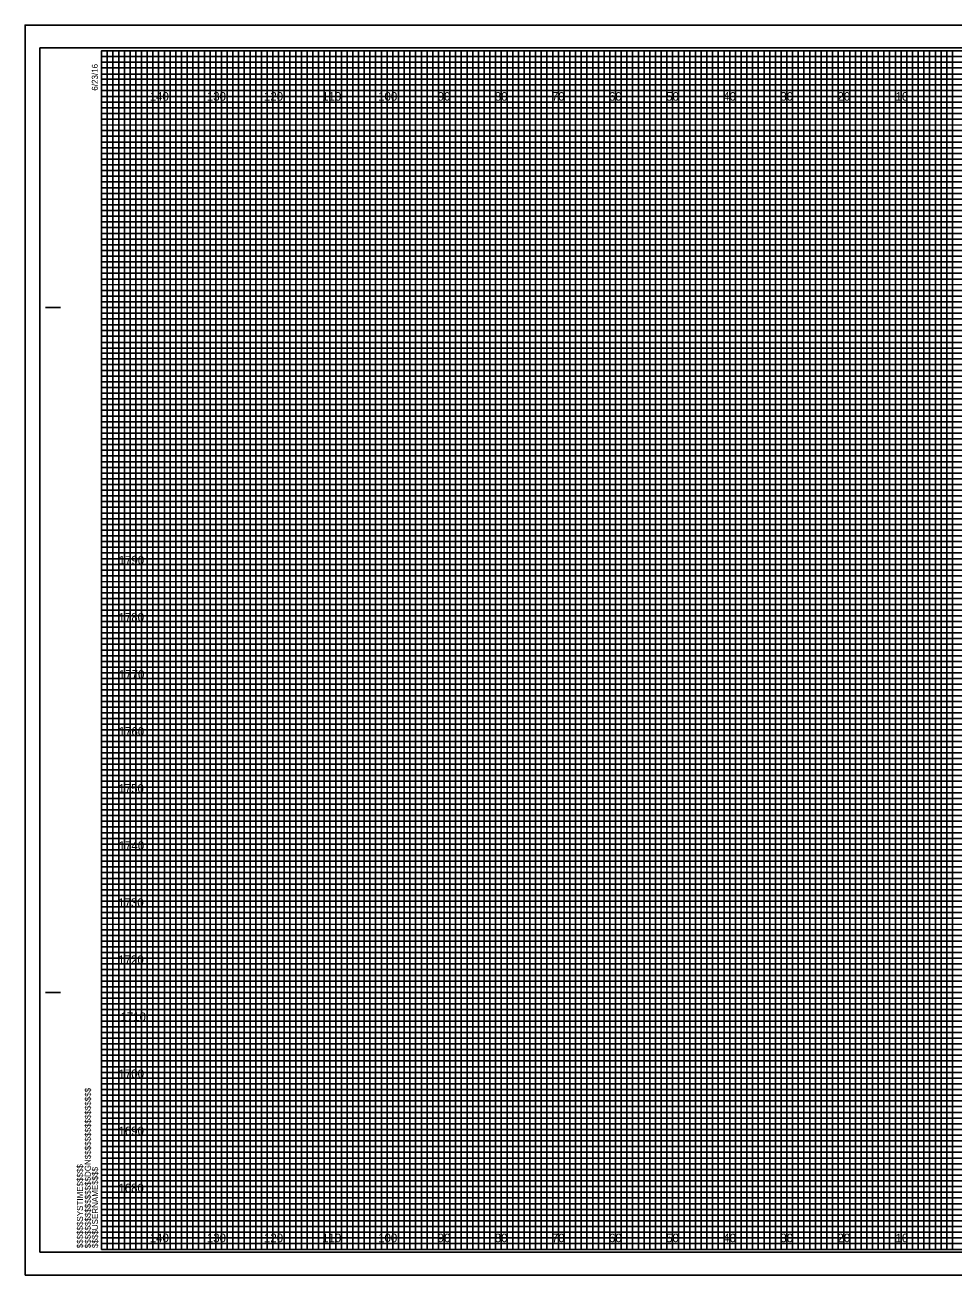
# Model space of a CAD drawing. Extents: x 1443 to 2205, y -29 to 5484.
# Drawn here: x 1867.8 to 2030.5, y 631.1 to 850.1 of the extents above; entities that cross this region are included whole.
import ezdxf

# ---------------------------------------------------------------- set-up
doc = ezdxf.new("R2010")
doc.units = 0
for name, color, linetype in [('Pattern 3', 7, 'Continuous'), ('Prop Retaining Wall', 7, 'Continuous'), ('Prop XS DDE Earthwork Shape', 7, 'Continuous'), ('Prop XS DDE Slope Text', 7, 'Continuous'), ('Prop XS DDE Text', 7, 'Continuous'), ('Prop XS Earthwork Shape', 7, 'Continuous'), ('Prop XS Retaining Wall', 7, 'Continuous'), ('Prop XS Station Labels', 7, 'Continuous'), ('Prop XS Temporary Shoring', 7, 'Continuous'), ('Raster_Level_0', 7, 'Continuous'), ('Scratch_Level_3', 7, 'Continuous')]:
    doc.layers.add(name, color=color, linetype=linetype)

msp = doc.modelspace()

# ---------------------------------------------------------------- linework, layer by layer
at = {"layer": 'Pattern 3'}
for p, q in [((2204.52, 850.05), (1867.82, 850.05)), ((1867.82, 850.05), (1867.82, 631.05)), ((1867.82, 631.05), (2204.52, 631.05))]:
    msp.add_line(p, q, dxfattribs=at)
at = {"layer": 'Prop Retaining Wall'}
for p, q in [((1881.22, 844.55), (2141.22, 844.55)), ((2141.22, 843.53), (1881.22, 843.53)), ((1881.22, 843.53), (1881.22, 842.55)), ((1881.22, 842.55), (2141.22, 842.55)), ((2141.22, 841.44), (1881.22, 841.44)), ((1881.22, 841.44), (1881.22, 839.55)), ((1881.22, 839.55), (2201.22, 839.55))]:
    msp.add_line(p, q, dxfattribs=at)
for points in [[(1881.22, 838.55), (2151.22, 838.55), (2201.22, 838.55), (2201.22, 837.55), (1881.22, 837.55)], [(1881.22, 836.55), (2201.22, 836.55), (2201.22, 834.55), (1881.22, 834.55)], [(1881.22, 833.55), (2201.22, 833.55), (2201.22, 832.55), (1881.22, 832.53)], [(1881.22, 831.55), (2201.22, 831.55), (2201.22, 829.55), (1881.22, 829.55)], [(1881.22, 828.55), (2201.22, 828.55), (2201.22, 827.55), (1881.22, 827.55)], [(1881.22, 826.55), (2201.22, 826.55), (2201.22, 824.55), (1881.22, 824.55)], [(1881.22, 823.55), (2201.22, 823.55), (2201.22, 822.55), (1881.22, 822.55)], [(1881.22, 821.55), (2201.22, 821.55), (2201.22, 819.55), (1881.22, 819.55)], [(1881.22, 818.55), (2201.22, 818.55), (2201.22, 817.55), (1881.22, 817.55)], [(1881.22, 816.55), (2201.22, 816.55), (2201.22, 814.55), (1881.22, 814.55)], [(1881.22, 813.55), (2201.22, 813.55), (2201.22, 812.55), (1881.22, 812.55)], [(1881.22, 811.55), (2201.22, 811.55), (2201.22, 809.5), (2201.22, 808.55), (2201.22, 807.55), (1881.22, 807.55)], [(1881.22, 809.55), (2201.22, 809.55), (2201.22, 808.55), (1881.22, 808.55)], [(1881.22, 806.55), (2201.22, 806.55), (2201.22, 804.55), (1881.22, 804.58)], [(1881.22, 804.58), (2201.22, 804.55), (2201.22, 803.55), (1881.22, 803.55)], [(1881.22, 802.55), (2201.22, 802.55), (2201.22, 801.55), (1881.22, 801.55)], [(1881.22, 799.55), (2201.22, 799.55), (2201.22, 798.55), (1881.22, 798.55)], [(1881.22, 797.55), (2201.22, 797.55), (2201.22, 796.55), (1881.22, 796.55)], [(1881.15, 794.44), (2201.22, 794.44), (2201.22, 793.43), (1881.15, 793.43)], [(1881.22, 792.55), (2201.22, 792.55), (2201.22, 791.55), (1881.22, 791.55)], [(1881.22, 789.55), (2201.22, 789.55), (2201.22, 788.55), (1881.22, 788.55)], [(1881.22, 787.55), (2201.22, 787.55), (2201.22, 786.55), (1881.22, 786.55)], [(1881.22, 784.55), (2201.22, 784.55), (2201.22, 783.55), (1881.22, 783.55)], [(1881.22, 782.55), (2201.22, 782.55), (2201.22, 781.55), (1881.22, 781.55)], [(1881.22, 779.55), (2201.22, 779.55), (2201.22, 778.55), (1881.22, 778.55)], [(1881.22, 777.55), (2201.22, 777.55), (2201.22, 776.55), (1881.22, 776.55)], [(1881.22, 774.55), (2201.22, 774.55), (2201.21, 773.53), (1881.22, 773.55)], [(1881.22, 772.55), (2201.22, 772.55), (2201.22, 771.55), (1881.22, 771.55)], [(1881.22, 769.55), (2201.22, 769.55), (2201.22, 768.55), (1881.22, 768.55)], [(1881.22, 767.55), (2201.22, 767.55), (2201.22, 766.55), (1881.22, 766.55)], [(1881.22, 764.55), (2201.22, 764.55), (2201.22, 763.55), (1881.22, 763.55)], [(1881.22, 762.55), (2201.22, 762.55), (2201.22, 761.55), (1881.22, 761.55)], [(1881.22, 759.55), (2201.22, 759.55), (2201.22, 758.55), (1881.22, 758.55)], [(1881.22, 757.55), (2201.22, 757.55), (2201.22, 756.55), (1881.22, 756.55)], [(1881.22, 754.55), (2201.22, 754.55), (2201.22, 753.55), (1881.22, 753.55)], [(1881.22, 752.54), (2201.29, 752.46), (2201.22, 751.55), (1881.22, 751.55)], [(1881.22, 749.55), (2201.22, 749.55), (2201.22, 748.55), (1881.22, 748.55)], [(1881.22, 747.55), (2201.22, 747.55), (2201.22, 746.55), (1881.22, 746.55)], [(1881.22, 744.55), (2201.22, 744.55), (2201.22, 743.55), (1881.22, 743.55)], [(1881.22, 742.55), (2201.22, 742.55), (2201.22, 741.55), (1881.22, 741.55)], [(1881.22, 739.55), (2201.22, 739.55), (2201.22, 738.55), (1881.22, 738.55)], [(1881.22, 737.55), (2201.22, 737.55), (2201.22, 736.55), (1881.22, 736.55)], [(1881.22, 734.55), (2201.22, 734.55), (2201.22, 733.55), (1881.22, 733.55)], [(1881.22, 732.55), (2201.22, 732.55), (2201.22, 731.55), (1881.22, 731.55)], [(1881.22, 729.55), (2201.22, 729.55), (2201.22, 728.55), (1881.22, 728.55)], [(1881.22, 727.55), (2201.22, 727.55), (2201.22, 726.55), (1881.22, 726.55)], [(1881.22, 724.55), (2201.22, 724.55), (2201.22, 723.55), (1881.22, 723.55)], [(1881.22, 722.55), (2201.22, 722.55), (2201.22, 721.55), (1881.22, 721.55)], [(1881.22, 719.55), (2201.22, 719.55), (2201.22, 718.55), (1881.22, 718.55)], [(1881.22, 717.55), (2201.22, 717.55), (2201.22, 716.55), (1881.22, 716.55)], [(1881.22, 714.55), (2201.22, 714.55), (2201.21, 713.53), (1881.22, 713.55)], [(1881.22, 712.55), (2201.22, 712.55), (2201.22, 711.55), (1881.22, 711.55)], [(1881.22, 709.55), (2201.22, 709.55), (2201.22, 708.55), (1881.22, 708.55)], [(1881.22, 707.55), (2201.22, 707.55), (2201.22, 706.55), (1881.22, 706.55)], [(1881.22, 704.55), (2201.22, 704.55), (2201.22, 703.55), (1881.22, 703.55)], [(1881.22, 702.55), (2201.22, 702.55), (2201.22, 701.55), (1881.22, 701.55)], [(1881.22, 699.55), (2201.22, 699.55), (2201.22, 698.55), (1881.22, 698.55)], [(1881.22, 697.55), (2201.22, 697.55), (2201.22, 696.55), (1881.22, 696.55)], [(1881.22, 694.55), (2201.22, 694.55), (2201.22, 693.55), (1881.22, 693.55)], [(1881.22, 692.54), (2201.29, 692.46), (2201.22, 691.55), (1881.22, 691.55)], [(1881.22, 689.55), (2201.22, 689.55), (2201.22, 688.55), (1881.22, 688.55)], [(1881.22, 687.55), (2201.22, 687.55), (2201.22, 686.55), (1881.22, 686.55)], [(1881.22, 684.55), (2201.22, 684.55), (2201.22, 683.55), (1881.22, 683.55)], [(1881.22, 682.55), (2201.22, 682.55), (2201.22, 681.55), (1881.22, 681.55)], [(1881.22, 679.55), (2201.22, 679.55), (2201.22, 678.55), (1881.22, 678.55)], [(1881.22, 677.55), (2201.22, 677.55), (2201.22, 676.55), (1881.22, 676.55)], [(1881.22, 674.55), (2201.22, 674.55), (2201.22, 673.55), (1881.22, 673.55)], [(1881.22, 672.55), (2201.22, 672.55), (2201.22, 671.55), (1881.22, 671.55)], [(1881.22, 669.55), (2201.22, 669.55), (2201.22, 668.55), (1881.22, 668.55)], [(1881.22, 667.55), (2201.22, 667.55), (2201.22, 666.55), (1881.22, 666.55)], [(1881.22, 664.55), (2201.22, 664.55), (2201.22, 663.55), (1881.22, 663.55)], [(1881.22, 662.55), (2201.22, 662.55), (2201.22, 661.55), (1881.22, 661.55)], [(1881.22, 659.55), (2201.22, 659.55), (2201.22, 658.55), (1881.22, 658.55)], [(1881.22, 657.55), (2201.22, 657.55), (2201.22, 656.55), (1881.22, 656.55)], [(1881.22, 654.55), (2201.22, 654.55), (2201.22, 653.55), (1881.22, 653.55)], [(1881.22, 652.55), (2201.22, 652.55), (2201.22, 651.55), (1881.22, 651.55)], [(1881.22, 649.55), (2201.22, 649.55), (2201.22, 648.55), (1881.22, 648.55)], [(1881.22, 647.55), (2201.22, 647.55), (2201.22, 646.55), (1881.22, 646.55)], [(1881.22, 644.55), (2201.22, 644.55), (2201.22, 643.55), (1881.22, 643.55)], [(1881.22, 642.55), (2201.22, 642.55), (2201.22, 641.55), (1881.22, 641.55)], [(1881.22, 639.55), (2201.22, 639.55), (2201.22, 638.55), (1881.22, 638.55)], [(1881.22, 637.55), (2201.22, 637.55), (2201.22, 636.55), (1881.22, 636.55)]]:
    msp.add_lwpolyline(points, dxfattribs=at)
at = {"layer": 'Prop XS DDE Earthwork Shape'}
msp.add_lwpolyline([(1870.42, 635.05), (2203.62, 635.05), (2203.62, 846.05), (1870.42, 846.05)], close=True, dxfattribs=at)
at = {"layer": 'Prop XS DDE Slope Text'}
for points in [[(1881.22, 635.55), (1882.22, 635.55), (1882.22, 845.55), (1883.22, 845.55), (1883.22, 635.55)], [(1883.22, 635.55), (1884.22, 635.55), (1884.22, 845.55), (1885.22, 845.55), (1885.22, 635.55)], [(1886.22, 635.55), (1887.22, 635.55), (1887.22, 845.55), (1888.22, 845.55), (1888.22, 635.55)], [(1888.22, 635.55), (1889.22, 635.55), (1889.22, 845.55), (1890.22, 845.55), (1890.22, 635.55)], [(1891.22, 635.55), (1892.22, 635.55), (1892.22, 845.55), (1893.22, 845.55), (1893.22, 635.55)], [(1893.22, 635.55), (1894.22, 635.55), (1894.22, 845.55), (1895.22, 845.55), (1895.22, 635.55)], [(1896.22, 635.55), (1897.22, 635.55), (1897.22, 845.55), (1898.22, 845.55), (1898.22, 635.55)], [(1898.22, 635.55), (1899.22, 635.55), (1899.22, 845.55), (1900.22, 845.55), (1900.22, 635.55)], [(1901.22, 635.55), (1902.22, 635.55), (1902.22, 845.55), (1903.22, 845.55), (1903.22, 635.55)], [(1903.22, 635.55), (1904.22, 635.55), (1904.22, 845.55), (1905.22, 845.55), (1905.22, 635.55)], [(1906.22, 635.55), (1907.22, 635.55), (1907.22, 845.55), (1908.22, 845.55), (1908.22, 635.55)], [(1908.22, 635.55), (1909.22, 635.55), (1909.22, 845.55), (1910.22, 845.55), (1910.22, 635.55)], [(1911.22, 635.55), (1912.22, 635.55), (1912.22, 845.55), (1913.22, 845.55), (1913.22, 635.55)], [(1913.22, 635.55), (1914.22, 635.55), (1914.22, 845.55), (1915.22, 845.55), (1915.22, 635.55)], [(1916.22, 635.55), (1917.22, 635.55), (1917.22, 845.55), (1918.22, 845.55), (1918.22, 635.55)], [(1918.22, 635.55), (1919.22, 635.55), (1919.22, 845.55), (1920.22, 845.55), (1920.22, 635.55)], [(1921.22, 635.55), (1922.22, 635.55), (1922.22, 845.55), (1923.22, 845.55), (1923.22, 635.55)], [(1923.22, 635.55), (1924.22, 635.55), (1924.22, 845.55), (1925.22, 845.55), (1925.22, 635.55)], [(1926.22, 635.55), (1927.22, 635.55), (1927.22, 845.55), (1928.22, 845.55), (1928.22, 635.55)], [(1928.22, 635.55), (1929.22, 635.55), (1929.22, 845.55), (1930.22, 845.55), (1930.22, 635.55)], [(1931.22, 635.55), (1932.22, 635.55), (1932.22, 845.55), (1933.22, 845.55), (1933.22, 635.55)], [(1933.22, 635.55), (1934.22, 635.55), (1934.22, 845.55), (1935.22, 845.55), (1935.22, 635.55)], [(1936.22, 635.55), (1937.22, 635.55), (1937.22, 845.55), (1938.22, 845.55), (1938.22, 635.55)], [(1938.22, 635.55), (1939.22, 635.55), (1939.22, 845.55), (1940.22, 845.55), (1940.22, 635.55)], [(1941.22, 635.55), (1942.22, 635.55), (1942.22, 845.55), (1943.22, 845.55), (1943.22, 635.55)], [(1943.22, 635.55), (1944.22, 635.55), (1944.22, 845.55), (1945.22, 845.55), (1945.22, 635.55)], [(1946.22, 635.55), (1947.22, 635.55), (1947.22, 845.55), (1948.22, 845.55), (1948.22, 635.55)], [(1948.22, 635.55), (1949.22, 635.55), (1949.22, 845.55), (1950.22, 845.55), (1950.22, 635.55)], [(1951.22, 635.55), (1952.22, 635.55), (1952.22, 845.55), (1953.22, 845.55), (1953.22, 635.55)], [(1953.22, 635.55), (1954.22, 635.55), (1954.22, 845.55), (1955.22, 845.55), (1955.22, 635.55)], [(1956.22, 635.55), (1957.22, 635.55), (1957.22, 845.55), (1958.22, 845.55), (1958.22, 635.55)], [(1958.22, 635.55), (1959.22, 635.55), (1959.22, 845.55), (1960.22, 845.55), (1960.22, 635.55)], [(1961.22, 635.55), (1962.22, 635.55), (1962.22, 845.55), (1963.22, 845.55), (1963.22, 635.55)], [(1963.22, 635.55), (1964.22, 635.55), (1964.22, 845.55), (1965.22, 845.55), (1965.22, 635.55)], [(1966.22, 635.55), (1967.22, 635.55), (1967.22, 845.55), (1968.22, 845.55), (1968.22, 635.55)], [(1968.22, 635.55), (1969.22, 635.55), (1969.22, 845.55), (1970.22, 845.55), (1970.22, 635.55)], [(1971.22, 635.55), (1972.22, 635.55), (1972.22, 845.55), (1973.22, 845.55), (1973.22, 635.55)], [(1973.22, 635.55), (1974.22, 635.55), (1974.22, 845.55), (1975.22, 845.55), (1975.22, 635.55)], [(1976.22, 635.55), (1977.22, 635.55), (1977.22, 845.55), (1978.22, 845.55), (1978.22, 635.55)], [(1978.22, 635.55), (1979.22, 635.55), (1979.22, 845.55), (1980.22, 845.55), (1980.22, 635.55)], [(1981.22, 635.55), (1982.22, 635.55), (1982.22, 845.55), (1983.22, 845.55), (1983.22, 635.55)], [(1983.22, 635.55), (1984.22, 635.55), (1984.22, 845.55), (1985.22, 845.55), (1985.22, 635.55)], [(1986.22, 635.55), (1987.22, 635.55), (1987.22, 845.55), (1988.22, 845.55), (1988.22, 635.55)], [(1988.22, 635.55), (1989.22, 635.55), (1989.22, 845.55), (1990.22, 845.55), (1990.22, 635.55)], [(1991.22, 635.55), (1992.22, 635.55), (1992.22, 845.55), (1993.22, 845.55), (1993.22, 635.55)], [(1993.22, 635.55), (1994.22, 635.55), (1994.22, 845.55), (1995.22, 845.55), (1995.22, 635.55)], [(1996.22, 635.55), (1997.22, 635.55), (1997.22, 845.55), (1998.22, 845.55), (1998.22, 635.55)], [(1998.22, 635.55), (1999.22, 635.55), (1999.22, 845.55), (2000.22, 845.55), (2000.22, 635.55)], [(2001.22, 635.55), (2002.22, 635.55), (2002.22, 845.55), (2003.22, 845.55), (2003.22, 635.55)], [(2003.22, 635.55), (2004.22, 635.55), (2004.22, 845.55), (2005.22, 845.55), (2005.22, 635.55)], [(2006.22, 635.55), (2007.22, 635.55), (2007.22, 845.55), (2008.22, 845.55), (2008.22, 635.55)], [(2008.22, 635.55), (2009.22, 635.55), (2009.22, 845.55), (2010.22, 845.55), (2010.22, 635.55)], [(2011.22, 635.55), (2012.22, 635.55), (2012.22, 845.55), (2013.22, 845.55), (2013.22, 635.55)], [(2013.22, 635.55), (2014.22, 635.55), (2014.22, 845.55), (2015.22, 845.55), (2015.22, 635.55)], [(2016.22, 635.55), (2017.22, 635.55), (2017.22, 845.55), (2018.22, 845.55), (2018.22, 635.55)], [(2018.22, 635.55), (2019.22, 635.55), (2019.22, 845.55), (2020.22, 845.55), (2020.22, 635.55)], [(2021.22, 635.55), (2022.22, 635.55), (2022.22, 845.55), (2023.22, 845.55), (2023.22, 635.55)], [(2023.22, 635.55), (2024.22, 635.55), (2024.22, 845.55), (2025.22, 845.55), (2025.22, 635.55)], [(2026.22, 635.55), (2027.22, 635.55), (2027.22, 845.55), (2028.22, 845.55), (2028.22, 635.55)], [(2028.22, 635.55), (2029.22, 635.55), (2029.22, 845.55), (2030.22, 845.55), (2030.22, 635.55)]]:
    msp.add_lwpolyline(points, dxfattribs=at)
at = {"layer": 'Prop XS DDE Text'}
msp.add_lwpolyline([(1867.82, 631.05), (2204.52, 631.05), (2204.52, 850.05), (1867.82, 850.05)], close=True, dxfattribs=at)
at = {"layer": 'Prop XS Earthwork Shape'}
for p, q in [((1891.22, 845.55), (1881.22, 845.55)), ((1891.22, 635.55), (1891.22, 845.55)), ((1911.22, 845.55), (1901.22, 845.55)), ((1901.22, 845.55), (1901.22, 635.55)), ((1911.22, 635.55), (1911.22, 845.55)), ((1931.22, 845.55), (1921.22, 845.55)), ((1921.22, 845.55), (1921.22, 635.55)), ((1931.22, 635.55), (1931.22, 845.55)), ((1951.22, 845.55), (1941.22, 845.55)), ((1941.22, 845.55), (1941.22, 635.55)), ((1951.22, 635.55), (1951.22, 845.55)), ((1971.22, 845.55), (1961.22, 845.55)), ((1961.22, 845.55), (1961.22, 635.55)), ((1971.22, 635.55), (1971.22, 845.55)), ((1991.22, 845.55), (1981.22, 845.55)), ((1981.22, 845.55), (1981.22, 635.55)), ((1991.22, 635.55), (1991.22, 845.55)), ((2011.22, 845.55), (2001.22, 845.55)), ((2001.22, 845.55), (2001.22, 635.55)), ((2011.22, 635.55), (2011.22, 845.55)), ((2031.22, 845.55), (2021.22, 845.55)), ((2021.22, 845.55), (2021.22, 635.55)), ((1901.22, 635.55), (1891.22, 635.55)), ((1921.22, 635.55), (1911.22, 635.55)), ((1941.22, 635.55), (1931.22, 635.55)), ((1961.22, 635.55), (1951.22, 635.55)), ((1981.22, 635.55), (1971.22, 635.55)), ((2001.22, 635.55), (1991.22, 635.55)), ((2021.22, 635.55), (2011.22, 635.55))]:
    msp.add_line(p, q, dxfattribs=at)
for points in [[(1881.22, 835.55), (2201.22, 835.55), (2201.22, 825.55), (1881.22, 825.55)], [(1881.22, 815.55), (2201.22, 815.55), (2201.22, 805.55), (1881.22, 805.55)], [(1881.22, 795.55), (2201.22, 795.55), (2201.22, 785.55), (1881.22, 785.55)], [(1881.22, 775.55), (2201.22, 775.55), (2201.22, 765.55), (1881.22, 765.55)], [(1881.22, 755.55), (2201.22, 755.55), (2201.22, 745.55), (1881.22, 745.55)], [(1881.22, 735.55), (2201.22, 735.55), (2201.22, 725.55), (1881.22, 725.55)], [(1881.22, 715.55), (2201.22, 715.55), (2201.22, 705.55), (1881.22, 705.55)], [(1881.22, 695.55), (2201.22, 695.55), (2201.22, 685.55), (1881.22, 685.55)], [(1881.22, 675.55), (2201.22, 675.55), (2201.22, 665.55), (1881.22, 665.55)], [(1881.22, 655.55), (2201.22, 655.55), (2201.22, 645.55), (1881.22, 645.55)]]:
    msp.add_lwpolyline(points, dxfattribs=at)
at = {"layer": 'Prop XS Retaining Wall'}
for p, q in [((1871.42, 800.55), (1873.92, 800.55)), ((1871.52, 800.55), (1874.02, 800.55)), ((1871.42, 680.55), (1873.92, 680.55)), ((1871.52, 680.55), (1874.02, 680.55)), ((1881.22, 635.55), (1881.22, 635.55)), ((1881.22, 635.55), (1881.22, 635.55)), ((1881.22, 635.55), (1881.22, 635.55)), ((1881.22, 635.55), (1881.22, 635.55)), ((1881.22, 635.55), (1881.22, 635.55)), ((1881.22, 635.55), (1881.22, 635.55)), ((1881.22, 635.55), (1881.22, 635.55))]:
    msp.add_line(p, q, dxfattribs=at)
msp.add_lwpolyline([(2201.22, 845.55), (1881.22, 845.55), (1881.22, 635.55), (2201.22, 635.55)], close=True, dxfattribs=at)
at = {"layer": 'Prop XS Station Labels'}
for points in [[(1881.22, 845.55), (1886.22, 845.55), (1886.22, 635.55), (1896.22, 635.55), (1896.22, 845.55), (1906.22, 845.55), (1906.22, 635.55), (1916.22, 635.55), (1916.22, 845.55), (1926.22, 845.55), (1926.22, 635.55), (1936.22, 635.55), (1936.22, 845.55), (1946.22, 845.55), (1946.22, 635.55), (1956.22, 635.55), (1956.22, 845.55), (1966.22, 845.55), (1966.22, 635.55), (1976.22, 635.55), (1976.22, 845.55), (1986.22, 845.55), (1986.22, 635.55), (1996.22, 635.55), (1996.22, 845.55), (2006.22, 845.55), (2006.22, 635.55), (2016.22, 635.55), (2016.22, 845.55), (2026.22, 845.55), (2026.22, 635.55), (2036.22, 635.55)], [(1881.22, 840.55), (2156.22, 840.55)], [(1881.22, 820.55), (2201.22, 820.55), (2201.22, 830.55), (1881.22, 830.55)], [(1881.22, 800.55), (2201.22, 800.55), (2201.22, 810.55), (1881.22, 810.55)], [(1881.22, 780.55), (2201.22, 780.55), (2201.22, 790.55), (1881.22, 790.55)], [(1881.22, 760.55), (2201.22, 760.55), (2201.22, 770.55), (1881.22, 770.55)], [(1881.22, 740.55), (2201.22, 740.55), (2201.22, 750.55), (1881.22, 750.55)], [(1881.22, 720.55), (2201.22, 720.55), (2201.22, 730.55), (1881.22, 730.55)], [(1881.22, 700.55), (2201.22, 700.55), (2201.22, 710.55), (1881.22, 710.55)], [(1881.22, 680.55), (2201.22, 680.55), (2201.22, 690.55), (1881.22, 690.55)], [(1881.22, 660.55), (2201.22, 660.55), (2201.22, 670.55), (1881.22, 670.55)], [(1881.22, 640.55), (2201.22, 640.55), (2201.22, 650.55), (1881.22, 650.55)]]:
    msp.add_lwpolyline(points, dxfattribs=at)
at = {"layer": 'Prop XS Temporary Shoring'}
for p, q in [((1891.22, 635.55), (1891.22, 845.55)), ((1901.22, 635.55), (1901.22, 845.55)), ((1911.22, 635.55), (1911.22, 845.55)), ((1921.22, 635.55), (1921.22, 845.55)), ((1931.22, 635.55), (1931.22, 845.55)), ((1941.22, 635.55), (1941.22, 845.55)), ((1951.22, 635.55), (1951.22, 845.55)), ((1961.22, 635.55), (1961.22, 845.55)), ((1971.22, 635.55), (1971.22, 845.55)), ((1981.22, 635.55), (1981.22, 845.55)), ((1991.22, 635.55), (1991.22, 845.55)), ((2001.22, 635.55), (2001.22, 845.55)), ((2011.22, 635.55), (2011.22, 845.55)), ((2021.22, 635.55), (2021.22, 845.55)), ((1881.22, 835.55), (2201.22, 835.55)), ((1881.22, 825.55), (2201.22, 825.55)), ((1881.22, 815.55), (2201.22, 815.55)), ((1881.22, 805.55), (2201.22, 805.55)), ((1881.22, 795.55), (2201.22, 795.55)), ((1881.22, 785.55), (2201.22, 785.55)), ((1881.22, 775.55), (2201.22, 775.55)), ((1881.22, 765.55), (2201.22, 765.55)), ((1881.22, 755.55), (2201.22, 755.55)), ((1881.22, 745.55), (2201.22, 745.55)), ((1881.22, 735.55), (2201.22, 735.55)), ((1881.22, 725.55), (2201.22, 725.55)), ((1881.22, 715.55), (2201.22, 715.55)), ((1881.22, 705.55), (2201.22, 705.55)), ((1881.22, 695.55), (2201.22, 695.55)), ((1881.22, 685.55), (2201.22, 685.55)), ((1881.22, 675.55), (2201.22, 675.55)), ((1881.22, 665.55), (2201.22, 665.55)), ((1881.22, 655.55), (2201.22, 655.55)), ((1881.22, 645.55), (2201.22, 645.55))]:
    msp.add_line(p, q, dxfattribs=at)

# ---------------------------------------------------------------- texts
at = {"layer": 'Prop XS Retaining Wall'}
for s, p in [('6/23/16', (1880.57, 838.55)), ('$$$$$$$$$$$$$$$$DGN$$$$$$$$$$$$$$$$', (1879.34, 635.73)), ('$$$$$$SYSTIME$$$$$', (1877.96, 635.73)), ('$$$$USERNAME$$$$', (1880.6, 635.78))]:
    msp.add_text(s, height=1.05, rotation=90, dxfattribs=at).set_placement(p)
at = {"layer": 'Raster_Level_0'}
for s, p in [('140', (1889.66, 836.8)), ('130', (1899.66, 836.8)), ('120', (1909.66, 836.8)), ('110', (1919.84, 836.8)), ('100', (1929.66, 836.8)), ('90', (1940.08, 836.8)), ('80', (1950.08, 836.8)), ('70', (1960.08, 836.8)), ('60', (1970.08, 836.8)), ('50', (1980.08, 836.8)), ('40', (1990.08, 836.8)), ('30', (2000.08, 836.8)), ('20', (2010.08, 836.8)), ('10', (2020.26, 836.8)), ('140', (1889.66, 636.8)), ('130', (1899.66, 636.8)), ('120', (1909.66, 636.8)), ('110', (1919.84, 636.8)), ('100', (1929.66, 636.8)), ('90', (1940.08, 636.8)), ('80', (1950.08, 636.8)), ('70', (1960.08, 636.8)), ('60', (1970.08, 636.8)), ('50', (1980.08, 636.8)), ('40', (1990.08, 636.8)), ('30', (2000.08, 636.8)), ('20', (2010.08, 636.8)), ('10', (2020.26, 636.8))]:
    msp.add_text(s, height=1.5, dxfattribs=at).set_placement(p)
at = {"layer": 'Scratch_Level_3'}
for s, p in [('1790', (1884.22, 755.55)), ('1780', (1884.2, 745.55)), ('1770', (1884.26, 735.55)), ('1760', (1884.22, 725.55)), ('1750', (1884.18, 715.55)), ('1740', (1884.22, 705.55)), ('1730', (1884.14, 695.55)), ('1720', (1884.15, 685.55)), ('1710', (1884.53, 675.55)), ('1700', (1884.2, 665.55)), ('1690', (1884.19, 655.55)), ('1680', (1884.17, 645.55))]:
    msp.add_text(s, height=1.5, dxfattribs=at).set_placement(p)

doc.saveas('drawing.dxf')
